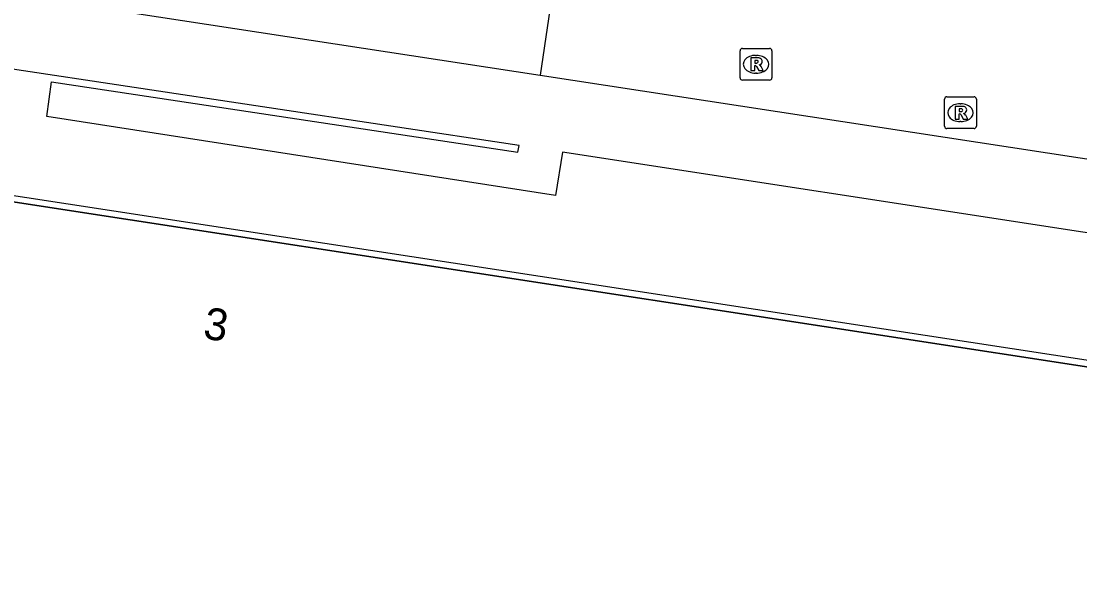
# Model space of a CAD drawing. Extents: x 161094 to 161705, y 379509 to 380907.
# Drawn here: x 161425.89 to 161459.2, y 380422.37 to 380439.94 of the extents above; entities that cross this region are included whole.
import ezdxf

# ---------------------------------------------------------------- set-up
doc = ezdxf.new("R2010")
doc.units = 0
for name, color, linetype in [('IMGEO_Pand', 7, 'Continuous'), ('IMGEO_Pand_nummerreeks', 7, 'Continuous'), ('IMGEO_Pand_overbouw', 7, 'Continuous'), ('IMGEO_Rioolput', 7, 'Continuous'), ('IMGEO_Voetpad_gesloten', 7, 'Continuous'), ('IMGEO_Voetpad_open', 7, 'Continuous')]:
    doc.layers.add(name, color=color, linetype=linetype)

msp = doc.modelspace()

# ---------------------------------------------------------------- linework, layer by layer
at = {"layer": 'IMGEO_Pand'}
msp.add_lwpolyline([(161415.881, 380435.194), (161415.964, 380435.735), (161391.176, 380439.506), (161383.009, 380385.949), (161464.836, 380373.488), (161472.988, 380426.991), (161418.398, 380435.368), (161418.318, 380434.848)], dxfattribs=at)
at = {"layer": 'IMGEO_Pand_overbouw'}
msp.add_lwpolyline([(161458.223, 380370.06), (161464.36, 380369.123), (161473.226, 380427.168), (161391.017, 380439.754), (161382.131, 380381.674), (161399.864, 380378.968), (161426.096, 380374.964), (161453.543, 380370.774)], close=True, dxfattribs=at)
msp.add_lwpolyline([(161418.318, 380434.848), (161418.398, 380435.368), (161472.988, 380426.991), (161464.836, 380373.488), (161383.009, 380385.949), (161391.176, 380439.506), (161415.964, 380435.735), (161415.881, 380435.194)], dxfattribs=at)
at = {"layer": 'IMGEO_Rioolput'}
for p, q in [((161448.512, 380438.16), (161448.512, 380439.012)), ((161448.587, 380439.086), (161449.439, 380439.086)), ((161449.513, 380439.012), (161449.513, 380438.16)), ((161449, 380438.866), (161449.025, 380438.866)), ((161449.023, 380438.306), (161448.998, 380438.306)), ((161449.439, 380438.086), (161448.587, 380438.086)), ((161454.944, 380436.637), (161454.944, 380437.489)), ((161455.019, 380437.563), (161455.871, 380437.563)), ((161455.432, 380437.343), (161455.457, 380437.343)), ((161455.945, 380437.489), (161455.945, 380436.637)), ((161455.455, 380436.783), (161455.43, 380436.783)), ((161455.871, 380436.563), (161455.019, 380436.563))]:
    msp.add_line(p, q, dxfattribs=at)
for points in [[(161448.512, 380438.16), (161448.512, 380439.012)], [(161448.587, 380439.086), (161449.439, 380439.086)], [(161449.513, 380439.012), (161449.513, 380438.16)], [(161449.101, 380438.784), (161448.849, 380438.786), (161448.849, 380438.386)], [(161449.027, 380438.705), (161448.973, 380438.705), (161448.973, 380438.624)], [(161448.973, 380438.624), (161449.025, 380438.624)], [(161448.849, 380438.386), (161448.973, 380438.386), (161448.973, 380438.548), (161448.984, 380438.548)], [(161449.031, 380438.519), (161449.102, 380438.386), (161449.242, 380438.386), (161449.177, 380438.512)], [(161449.439, 380438.086), (161448.587, 380438.086)], [(161454.944, 380436.637), (161454.944, 380437.489)], [(161455.019, 380437.563), (161455.871, 380437.563)], [(161455.945, 380437.489), (161455.945, 380436.637)], [(161455.533, 380437.261), (161455.281, 380437.263), (161455.281, 380436.863)], [(161455.281, 380436.863), (161455.405, 380436.863), (161455.405, 380437.025), (161455.416, 380437.025)], [(161455.459, 380437.182), (161455.405, 380437.182), (161455.405, 380437.101)], [(161455.405, 380437.101), (161455.457, 380437.101)], [(161455.463, 380436.996), (161455.534, 380436.863), (161455.674, 380436.863), (161455.609, 380436.989)], [(161455.871, 380436.563), (161455.019, 380436.563)]]:
    msp.add_lwpolyline(points, dxfattribs=at)
for centre, radius, start, end in [((161448.589, 380439.01), 0.0765, 91.552, 178.448), ((161448.589, 380439.01), 0.0765, 91.552, 178.448), ((161449.437, 380439.01), 0.0765, 1.552, 88.448), ((161449.437, 380439.01), 0.0765, 1.552, 88.448), ((161449.009, 380438.813), 0.19, 274.7715, 282.9687), ((161449.033, 380438.609), 0.0964, 77.0061, 93.1865), ((161449.047, 380438.666), 0.0378, 276.6634, 79.6772), ((161449.1, 380438.674), 0.109, 350.3612, 89.416), ((161449.098, 380438.674), 0.112, 277.5842, 350.9817), ((161448.983, 380438.495), 0.0533, 26.0293, 88.6989), ((161449.082, 380438.459), 0.108, 29.5134, 73.7905), ((161448.589, 380438.162), 0.0765, 181.552, 268.448), ((161448.589, 380438.162), 0.0765, 181.552, 268.448), ((161449.437, 380438.162), 0.0765, 271.552, 358.448), ((161449.437, 380438.162), 0.0765, 271.552, 358.448), ((161455.021, 380437.487), 0.0765, 91.552, 178.448), ((161455.021, 380437.487), 0.0765, 91.552, 178.448), ((161455.869, 380437.487), 0.0765, 1.552, 88.448), ((161455.869, 380437.487), 0.0765, 1.552, 88.448), ((161455.415, 380436.972), 0.0533, 26.0293, 88.6989), ((161455.441, 380437.29), 0.19, 274.7715, 282.9687), ((161455.465, 380437.086), 0.0964, 77.0061, 93.1865), ((161455.479, 380437.143), 0.0378, 276.6634, 79.6772), ((161455.532, 380437.151), 0.109, 350.3612, 89.416), ((161455.53, 380437.151), 0.112, 277.5842, 350.9817), ((161455.514, 380436.936), 0.108, 29.5134, 73.7905), ((161455.021, 380436.639), 0.0765, 181.552, 268.448), ((161455.021, 380436.639), 0.0765, 181.552, 268.448), ((161455.869, 380436.639), 0.0765, 271.552, 358.448), ((161455.869, 380436.639), 0.0765, 271.552, 358.448)]:
    msp.add_arc(centre, radius, start, end, dxfattribs=at)
for centre, major_axis, ratio, start_param, end_param in [((161448.999, 380438.586), (-0.387, 0.002), 0.722429, 4.712389, 7.853982), ((161449.024, 380438.586), (-0.39, 0.002), 0.717154, 1.570796, 4.712389), ((161455.431, 380437.063), (-0.387, 0.002), 0.722429, 4.712389, 7.853982), ((161455.456, 380437.063), (-0.39, 0.002), 0.717154, 1.570796, 4.712389)]:
    msp.add_ellipse(centre, major_axis=major_axis, ratio=ratio, start_param=start_param, end_param=end_param, dxfattribs=at)
at = {"layer": 'IMGEO_Voetpad_gesloten'}
for points in [[(161443.393, 380446.183), (161442.217, 380438.238)], [(161405.292, 380443.896), (161442.217, 380438.238)], [(161472.927, 380397.636), (161470.633, 380397.978), (161475.669, 380430.786), (161442.92, 380435.825), (161442.702, 380434.464), (161426.695, 380436.945), (161426.845, 380438.036), (161441.518, 380435.817), (161441.558, 380436.032), (161425.407, 380438.468)], [(161442.217, 380438.238), (161478.261, 380432.731), (161477.122, 380425.066), (161489.343, 380423.181)]]:
    msp.add_lwpolyline(points, dxfattribs=at)
at = {"layer": 'IMGEO_Voetpad_open'}
msp.add_lwpolyline([(161458.223, 380370.06), (161464.36, 380369.123), (161473.226, 380427.168), (161391.017, 380439.754), (161382.131, 380381.674), (161399.864, 380378.968)], dxfattribs=at)

# ---------------------------------------------------------------- texts
at = {"layer": 'IMGEO_Pand_nummerreeks'}
msp.add_text('3', height=1, rotation=351.3896, dxfattribs=at).set_placement((161431.587, 380429.969))

doc.saveas('drawing.dxf')
